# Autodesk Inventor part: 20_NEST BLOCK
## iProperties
Created: 2006-12
Part Number: 20_NEST BLOCK
Document SubType Name: Modeling
Designer: RDGodetteII
Material: Steel, High Strength Low Alloy
Mass: 2472.33 g
Surface Area: 388.175 cm^2
Volume: 315.349 cm^3
Density: 7.84 g/cm^3
Author: RDGodetteII
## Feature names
1. Extrusion1
2. Hole2
3. Rectangular Pattern2
